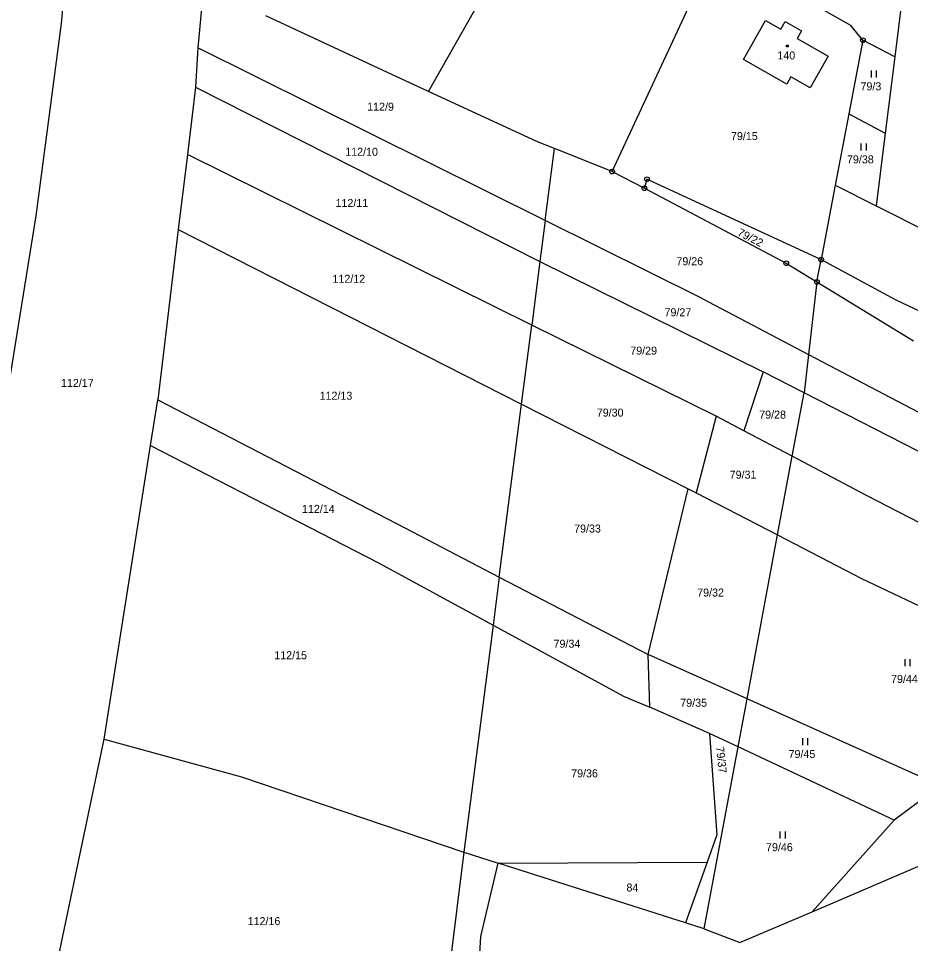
# Model space of a CAD drawing. Extents: x -794142 to -791199, y -1109267 to -1105626.
# Drawn here: x -793649.2 to -793459.6, y -1108185.5 to -1107988.9 of the extents above; entities that cross this region are included whole.
import ezdxf

# ---------------------------------------------------------------- set-up
doc = ezdxf.new("R2010")
doc.units = 0
for name, color, linetype in [('Vrstva 1', 7, 'Continuous'), ('Vrstva 14', 7, 'Continuous'), ('Vrstva 15', 7, 'Continuous'), ('Vrstva 23', 7, 'Continuous'), ('Vrstva 25', 7, 'Continuous'), ('Vrstva 28', 7, 'Continuous')]:
    doc.layers.add(name, color=color, linetype=linetype)

msp = doc.modelspace()

# ---------------------------------------------------------------- linework, layer by layer
at = {"layer": 'Vrstva 1'}
for p, q in [((-793636.68, -1107948.35), (-793640.1, -1107990)), ((-793562.05, -1108004.47), (-793534.31, -1107955.37)), ((-793523.03, -1108021.45), (-793500.99, -1107974.19)), ((-793472.28, -1107990.41), (-793500.99, -1107974.19)), ((-793609.89, -1107982.22), (-793611.09, -1107995.15)), ((-793461.03, -1107981.37), (-793462.96, -1107997.07)), ((-793569.72, -1108000.92), (-793596.59, -1107988.41)), ((-793640.1, -1107990), (-793645.52, -1108030.9)), ((-793495.1, -1107997.67), (-793490.42, -1107989.38)), ((-793490.42, -1107989.38), (-793487.17, -1107991.22)), ((-793487.17, -1107991.22), (-793486.24, -1107989.59)), ((-793486.24, -1107989.59), (-793482.75, -1107991.58)), ((-793469.71, -1107993.56), (-793472.28, -1107990.41)), ((-793482.75, -1107991.58), (-793483.67, -1107993.21)), ((-793483.67, -1107993.21), (-793477.12, -1107996.91)), ((-793469.71, -1107993.56), (-793472.69, -1108009.18)), ((-793462.96, -1107997.07), (-793469.71, -1107993.56)), ((-793611.09, -1107995.15), (-793611.57, -1108003.53)), ((-793537.25, -1108031.85), (-793611.09, -1107995.15)), ((-793477.12, -1107996.91), (-793480.92, -1108003.67)), ((-793485.92, -1108002.86), (-793495.1, -1107997.67)), ((-793462.96, -1107997.07), (-793464.96, -1108013.32)), ((-793562.05, -1108004.47), (-793569.72, -1108000.92)), ((-793485.06, -1108001.33), (-793485.92, -1108002.86)), ((-793480.92, -1108003.67), (-793485.06, -1108001.33)), ((-793611.57, -1108003.53), (-793613.28, -1108017.87)), ((-793611.57, -1108003.53), (-793538.37, -1108040.55)), ((-793538.88, -1108015.17), (-793562.05, -1108004.47)), ((-793472.69, -1108009.18), (-793475.58, -1108024.33)), ((-793472.69, -1108009.18), (-793464.96, -1108013.32)), ((-793464.96, -1108013.32), (-793466.87, -1108028.77)), ((-793535.29, -1108016.59), (-793538.88, -1108015.17)), ((-793613.28, -1108017.87), (-793615.26, -1108033.8)), ((-793540.11, -1108054.06), (-793613.28, -1108017.87)), ((-793537.25, -1108031.85), (-793535.29, -1108016.59)), ((-793523.03, -1108021.45), (-793535.29, -1108016.59)), ((-793523.03, -1108021.45), (-793516.14, -1108025.01)), ((-793516.14, -1108025.01), (-793515.6, -1108023.11)), ((-793515.6, -1108023.11), (-793478.6, -1108040.15)), ((-793475.58, -1108024.33), (-793478.6, -1108040.15)), ((-793475.58, -1108024.33), (-793466.87, -1108028.77)), ((-793516.14, -1108025.01), (-793486, -1108040.95)), ((-793466.87, -1108028.77), (-793433.49, -1108045.51)), ((-793645.52, -1108030.9), (-793662.6, -1108136.74)), ((-793537.25, -1108031.85), (-793538.37, -1108040.55)), ((-793503.9, -1108048.43), (-793537.25, -1108031.85)), ((-793615.26, -1108033.8), (-793619.58, -1108069.92)), ((-793615.26, -1108033.8), (-793542.27, -1108070.85)), ((-793538.37, -1108040.55), (-793540.11, -1108054.06)), ((-793538.37, -1108040.55), (-793490.95, -1108064.02)), ((-793486, -1108040.95), (-793479.51, -1108044.92)), ((-793479.51, -1108044.92), (-793478.6, -1108040.15)), ((-793478.6, -1108040.15), (-793462.7, -1108048.73)), ((-793479.51, -1108044.92), (-793481.29, -1108060.32)), ((-793479.51, -1108044.92), (-793458.99, -1108057.42)), ((-793503.9, -1108048.43), (-793481.29, -1108060.32)), ((-793462.7, -1108048.73), (-793414.62, -1108071.62)), ((-793542.27, -1108070.85), (-793540.11, -1108054.06)), ((-793500.91, -1108073.45), (-793540.11, -1108054.06)), ((-793481.29, -1108060.32), (-793482.23, -1108068.48)), ((-793481.29, -1108060.32), (-793418.17, -1108093.5)), ((-793490.95, -1108064.02), (-793494.99, -1108076.53)), ((-793482.23, -1108068.48), (-793490.95, -1108064.02)), ((-793484.74, -1108081.95), (-793482.23, -1108068.48)), ((-793419.32, -1108100.59), (-793482.23, -1108068.48)), ((-793621.12, -1108079.66), (-793619.58, -1108069.92)), ((-793619.58, -1108069.92), (-793566.96, -1108097.24)), ((-793546.99, -1108107.61), (-793542.27, -1108070.85)), ((-793542.27, -1108070.85), (-793506.86, -1108088.83)), ((-793500.91, -1108073.45), (-793505.16, -1108089.71)), ((-793494.99, -1108076.53), (-793500.91, -1108073.45)), ((-793484.74, -1108081.95), (-793494.99, -1108076.53)), ((-793630.96, -1108142.04), (-793621.12, -1108079.66)), ((-793621.12, -1108079.66), (-793572.65, -1108104.57)), ((-793487.85, -1108098.67), (-793484.74, -1108081.95)), ((-793468.95, -1108090.3), (-793484.74, -1108081.95)), ((-793515.35, -1108124.03), (-793506.86, -1108088.83)), ((-793506.86, -1108088.83), (-793505.16, -1108089.71)), ((-793505.16, -1108089.71), (-793487.85, -1108098.67)), ((-793421.6, -1108114.66), (-793468.95, -1108090.3)), ((-793566.96, -1108097.24), (-793546.99, -1108107.61)), ((-793494.33, -1108133.48), (-793487.85, -1108098.67)), ((-793487.85, -1108098.67), (-793470.04, -1108107.88)), ((-793572.65, -1108104.57), (-793548.3, -1108117.82)), ((-793546.99, -1108107.61), (-793548.3, -1108117.82)), ((-793546.99, -1108107.61), (-793515.35, -1108124.03)), ((-793470.04, -1108107.88), (-793424.06, -1108129.83)), ((-793548.3, -1108117.82), (-793554.5, -1108166.08)), ((-793548.3, -1108117.82), (-793520.44, -1108132.97)), ((-793515.03, -1108135.22), (-793515.35, -1108124.03)), ((-793494.33, -1108133.48), (-793515.35, -1108124.03)), ((-793520.44, -1108132.97), (-793515.03, -1108135.22)), ((-793496.23, -1108143.7), (-793494.33, -1108133.48)), ((-793453.28, -1108151.93), (-793494.33, -1108133.48)), ((-793502.29, -1108140.85), (-793515.03, -1108135.22)), ((-793642.75, -1108198.24), (-793630.96, -1108142.04)), ((-793630.96, -1108142.04), (-793601.77, -1108150.07)), ((-793502.29, -1108140.85), (-793500.73, -1108162.38)), ((-793496.23, -1108143.7), (-793502.29, -1108140.85)), ((-793503.42, -1108182.36), (-793496.23, -1108143.7)), ((-793463.11, -1108159.25), (-793496.23, -1108143.7)), ((-793601.77, -1108150.07), (-793554.5, -1108166.08)), ((-793480.52, -1108178.71), (-793415.67, -1108150.95)), ((-793453.28, -1108151.93), (-793463.11, -1108159.25)), ((-793463.11, -1108159.25), (-793480.52, -1108178.71)), ((-793500.73, -1108162.38), (-793502.82, -1108168.21)), ((-793554.5, -1108166.08), (-793561.21, -1108218.88)), ((-793554.5, -1108166.08), (-793547.2, -1108168.41)), ((-793550.94, -1108183.97), (-793547.2, -1108168.41)), ((-793547.2, -1108168.41), (-793502.82, -1108168.21)), ((-793507.44, -1108181.08), (-793547.2, -1108168.41)), ((-793502.82, -1108168.21), (-793507.44, -1108181.08)), ((-793495.84, -1108185.26), (-793480.52, -1108178.71)), ((-793503.42, -1108182.36), (-793507.44, -1108181.08)), ((-793503.42, -1108182.36), (-793495.84, -1108185.26)), ((-793552.16, -1108205.45), (-793550.94, -1108183.97))]:
    msp.add_line(p, q, dxfattribs=at)
at = {"layer": 'Vrstva 23'}
for p, q in [((-793467.92, -1108001.5), (-793467.92, -1108000)), ((-793466.92, -1108000), (-793466.92, -1108001.5)), ((-793470.06, -1108017.02), (-793470.06, -1108015.52)), ((-793469.06, -1108015.52), (-793469.06, -1108017.02)), ((-793460.72, -1108126.52), (-793460.72, -1108125.02)), ((-793459.72, -1108125.02), (-793459.72, -1108126.52)), ((-793482.46, -1108143.34), (-793482.46, -1108141.84)), ((-793481.46, -1108141.84), (-793481.46, -1108143.34)), ((-793487.27, -1108163.14), (-793487.27, -1108161.64)), ((-793486.27, -1108161.64), (-793486.27, -1108163.14))]:
    msp.add_line(p, q, dxfattribs=at)
at = {"layer": 'Vrstva 25'}
for p, q in [((-793485.93, -1107994.63), (-793485.63, -1107994.63)), ((-793485.93, -1107994.93), (-793485.93, -1107994.63)), ((-793485.63, -1107994.93), (-793485.93, -1107994.93)), ((-793485.63, -1107994.63), (-793485.63, -1107994.93))]:
    msp.add_line(p, q, dxfattribs=at)
at = {"layer": 'Vrstva 28'}
for centre, radius in [((-793469.71, -1107993.56), 0.5), ((-793469.71, -1107993.56), 0.01), ((-793523.03, -1108021.45), 0.5), ((-793523.03, -1108021.45), 0.01), ((-793515.6, -1108023.11), 0.5), ((-793515.6, -1108023.11), 0.01), ((-793516.14, -1108025.01), 0.5), ((-793516.14, -1108025.01), 0.01), ((-793478.6, -1108040.15), 0.5), ((-793478.6, -1108040.15), 0.01), ((-793486, -1108040.95), 0.5), ((-793486, -1108040.95), 0.01), ((-793479.51, -1108044.92), 0.5), ((-793479.51, -1108044.92), 0.01)]:
    msp.add_circle(centre, radius, dxfattribs=at)

# ---------------------------------------------------------------- texts
at = {"layer": 'Vrstva 14'}
for s, p in [('79/3', (-793470.227, -1108004.2)), ('112/9', (-793575.076, -1108008.53)), ('79/15', (-793497.756, -1108014.77)), ('112/10', (-793579.739, -1108018.11)), ('79/38', (-793473.106, -1108019.72)), ('112/11', (-793581.803, -1108028.99)), ('79/26', (-793509.356, -1108041.36)), ('112/12', (-793582.449, -1108045.09)), ('79/27', (-793511.883, -1108052.2)), ('79/29', (-793519.156, -1108060.35)), ('112/17', (-793640.146, -1108067.21)), ('112/13', (-793585.189, -1108069.93)), ('79/30', (-793526.276, -1108073.52)), ('79/28', (-793491.756, -1108073.94)), ('79/31', (-793498.03, -1108086.7)), ('112/14', (-793588.925, -1108093.97)), ('79/33', (-793531.097, -1108098.15)), ('79/32', (-793504.946, -1108111.74)), ('79/34', (-793535.462, -1108122.62)), ('112/15', (-793594.816, -1108125.06)), ('79/44', (-793463.738, -1108130.1)), ('79/35', (-793508.533, -1108135.16)), ('79/45', (-793485.519, -1108146.04)), ('79/36', (-793531.717, -1108150.15)), ('79/46', (-793490.312, -1108165.84)), ('84', (-793519.972, -1108174.41)), ('112/16', (-793600.479, -1108181.55))]:
    msp.add_text(s, height=1.7, dxfattribs=at).set_placement(p)
for s, rotation, p in [('79/22', 332.9487, (-793496.54, -1108034.946)), ('79/37', 276.00525, (-793500.937, -1108143.696))]:
    msp.add_text(s, height=1.7, rotation=rotation, dxfattribs=at).set_placement(p)
at = {"layer": 'Vrstva 15'}
msp.add_text('140', height=1.7, dxfattribs=at).set_placement((-793487.895, -1107997.64))

doc.saveas('drawing.dxf')
